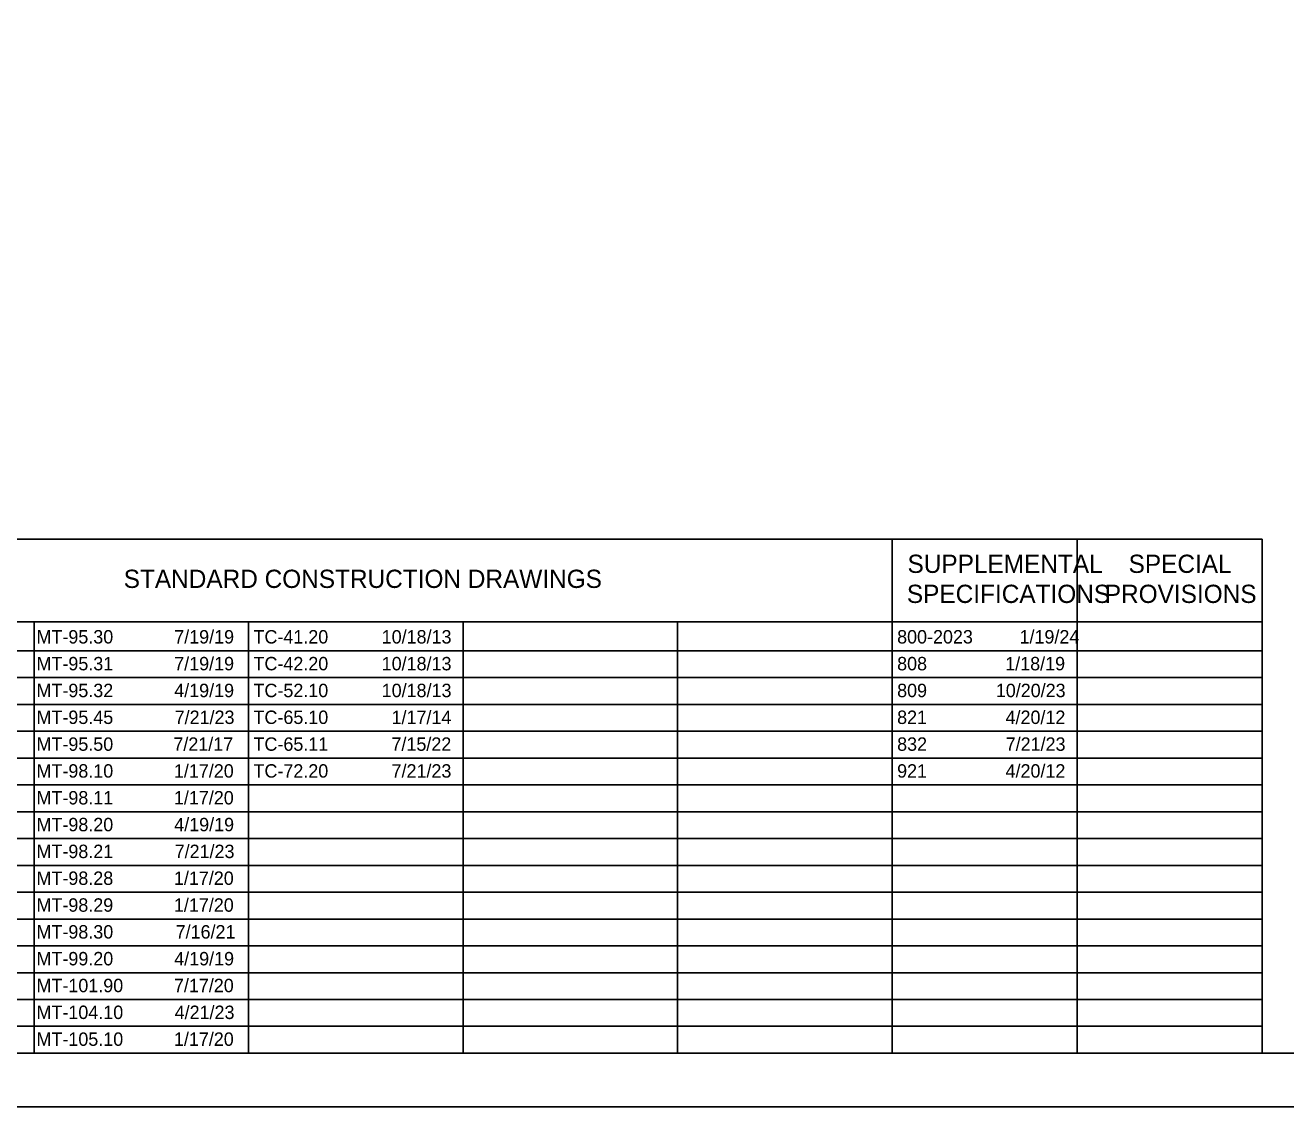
# Model space of a CAD drawing. Extents: x 0 to 34, y 0 to 22.
# Drawn here: x 12.07 to 23.82, y 0 to 10.08 of the extents above; entities that cross this region are included whole.
import ezdxf

# ---------------------------------------------------------------- set-up
doc = ezdxf.new("R2010")
doc.units = 0
for name, color, linetype in [('Default', 7, 'Continuous'), ('SH_Border', 7, 'Continuous'), ('SH_Cut_Line', 7, 'Continuous'), ('SH_Data', 7, 'Continuous'), ('SH_Text', 7, 'Continuous')]:
    doc.layers.add(name, color=color, linetype=linetype)

msp = doc.modelspace()

# ---------------------------------------------------------------- linework, layer by layer
at = {"layer": 'SH_Border'}
msp.add_lwpolyline([(1.5, 21.5), (33.5, 21.5), (33.5, 0.5), (1.5, 0.5)], close=True, dxfattribs=at)
at = {"layer": 'SH_Cut_Line'}
msp.add_lwpolyline([(0, 0), (34, 0), (34, 22), (0, 22)], close=True, dxfattribs=at)
at = {"layer": 'SH_Data'}
for p, q in [((10.15, 5.292), (23.6, 5.292)), ((20.15, 0.5), (20.15, 5.292)), ((21.875, 0.5), (21.875, 5.292)), ((23.6, 0.5), (23.6, 5.292)), ((10.15, 4.521), (23.6, 4.521)), ((12.15, 0.5), (12.15, 4.521)), ((14.15, 0.5), (14.15, 4.521)), ((16.15, 0.5), (16.15, 4.521)), ((18.15, 0.5), (18.15, 4.521)), ((10.15, 4.25), (23.6, 4.25)), ((10.15, 4), (23.6, 4)), ((10.15, 3.75), (23.6, 3.75)), ((10.15, 3.5), (23.6, 3.5)), ((10.15, 3.25), (23.6, 3.25)), ((10.15, 3), (23.6, 3)), ((10.15, 2.75), (23.6, 2.75)), ((10.15, 2.5), (23.6, 2.5)), ((10.15, 2.25), (23.6, 2.25)), ((10.15, 2), (23.6, 2)), ((10.15, 1.75), (23.6, 1.75)), ((10.15, 1.5), (23.6, 1.5)), ((10.15, 1.25), (23.6, 1.25)), ((10.15, 1), (23.6, 1)), ((10.15, 0.75), (23.6, 0.75))]:
    msp.add_line(p, q, dxfattribs=at)

# ---------------------------------------------------------------- texts
at = {"layer": 'Default'}
for s, p in [('MT-95.30', (12.173, 4.318)), ('7/19/19', (13.457, 4.318)), ('TC-41.20', (14.196, 4.318)), ('10/18/13', (15.391, 4.318)), ('800-2023', (20.196, 4.318)), ('1/19/24', (21.337, 4.318)), ('MT-95.31', (12.173, 4.068)), ('7/19/19', (13.457, 4.068)), ('TC-42.20', (14.196, 4.068)), ('10/18/13', (15.391, 4.068)), ('808', (20.196, 4.068)), ('1/18/19', (21.204, 4.068)), ('MT-95.32', (12.173, 3.818)), ('4/19/19', (13.457, 3.818)), ('TC-52.10', (14.196, 3.818)), ('10/18/13', (15.391, 3.818)), ('809', (20.196, 3.818)), ('10/20/23', (21.116, 3.818)), ('MT-95.45', (12.173, 3.568)), ('7/21/23', (13.461, 3.568)), ('TC-65.10', (14.196, 3.568)), ('1/17/14', (15.483, 3.568)), ('821', (20.196, 3.568)), ('4/20/12', (21.207, 3.568)), ('MT-95.50', (12.173, 3.318)), ('7/21/17', (13.449, 3.318)), ('TC-65.11', (14.196, 3.318)), ('7/15/22', (15.482, 3.318)), ('832', (20.196, 3.318)), ('7/21/23', (21.208, 3.318)), ('MT-98.10', (12.173, 3.068)), ('1/17/20', (13.454, 3.068)), ('TC-72.20', (14.196, 3.068)), ('7/21/23', (15.483, 3.068)), ('921', (20.196, 3.068)), ('4/20/12', (21.207, 3.068)), ('MT-98.11', (12.173, 2.818)), ('1/17/20', (13.454, 2.818)), ('MT-98.20', (12.173, 2.568)), ('4/19/19', (13.457, 2.568)), ('MT-98.21', (12.173, 2.318)), ('7/21/23', (13.461, 2.318)), ('MT-98.28', (12.173, 2.068)), ('1/17/20', (13.454, 2.068)), ('MT-98.29', (12.173, 1.818)), ('1/17/20', (13.454, 1.818)), ('MT-98.30', (12.173, 1.568)), ('7/16/21', (13.47, 1.568)), ('MT-99.20', (12.173, 1.318)), ('4/19/19', (13.457, 1.318)), ('MT-101.90', (12.173, 1.068)), ('7/17/20', (13.454, 1.068)), ('MT-104.10', (12.173, 0.818)), ('4/21/23', (13.461, 0.818)), ('MT-105.10', (12.173, 0.568)), ('1/17/20', (13.454, 0.568))]:
    msp.add_text(s, height=0.125, dxfattribs=at).set_placement(p)
at = {"layer": 'SH_Text'}
for s, p in [('SUPPLEMENTAL', (20.293, 4.976)), ('SPECIAL', (22.354, 4.976)), ('STANDARD CONSTRUCTION DRAWINGS', (12.986, 4.836)), ('SPECIFICATIONS', (20.287, 4.696)), ('PROVISIONS', (22.132, 4.696))]:
    msp.add_text(s, height=0.17, dxfattribs=at).set_placement(p)

doc.saveas('drawing.dxf')
